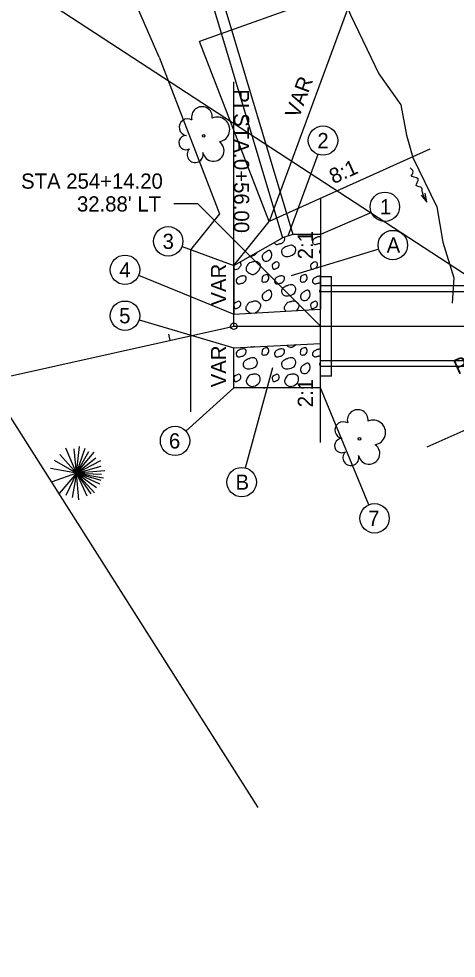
# Model space of a CAD drawing. Extents: x -1270 to 3371, y -118 to 220.
# Drawn here: x -1179.1 to -1138.8, y -9.7 to 76.8 of the extents above; entities that cross this region are included whole.
import ezdxf

# ---------------------------------------------------------------- set-up
doc = ezdxf.new("R2010")
doc.units = 0
for name, color, linetype in [('Default', 7, 'Continuous'), ('DR_P_Culvert', 7, 'Continuous'), ('GE_P_Alignment', 7, 'Continuous'), ('GE_P_Alignment_100_Bearings', 7, 'Continuous'), ('GE_P_Alignment_100_Distances', 7, 'Continuous'), ('MT_P_Edge_Line', 7, 'Continuous'), ('PF_P_Grade_Line', 7, 'Continuous'), ('PV_P_EOP', 7, 'Continuous'), ('TX_P_1', 7, 'Continuous')]:
    doc.layers.add(name, color=color, linetype=linetype)

msp = doc.modelspace()

# ---------------------------------------------------------------- linework, layer by layer
at = {"layer": 'Default'}
for p, q in [((-1166.155, 73.305), (-1175.043, 93.789)), ((-1147.999, 79.877), (-1162.424, 74.747)), ((-1147.999, 79.877), (-1156.01, 58.149)), ((-1141.191, 64.819), (-1156.01, 58.149)), ((-1151.28, 60.278), (-1151.28, 50.1)), ((-1163.28, 55.548), (-1163.28, 40.625)), ((-1159.28, 54.127), (-1159.28, 49.628)), ((-1159.28, 49.628), (-1151.28, 50.1)), ((-1213.942, 36.346), (-1159.28, 48.517)), ((-1159.28, 48.517), (-1045.28, 48.517)), ((-1157.013, 4.225), (-1184.627, 47.658)), ((-1159.28, 46.537), (-1151.28, 46.933)), ((-1151.28, 37.813), (-1151.28, 46.933)), ((-1159.28, 42.837), (-1159.28, 46.537)), ((-1131.014, 42.059), (-1141.492, 37.394)), ((-1173.764, 34.992), (-1174.76, 37.286)), ((-1173.764, 34.992), (-1173.995, 37.235)), ((-1173.764, 34.992), (-1173.485, 37.437)), ((-1173.764, 34.992), (-1172.98, 37.297)), ((-1173.764, 34.992), (-1175.312, 36.698)), ((-1173.764, 34.992), (-1172.648, 37.001)), ((-1173.764, 34.992), (-1172.157, 36.925)), ((-1173.764, 34.992), (-1171.978, 36.412)), ((-1173.764, 34.992), (-1175.809, 36.154)), ((-1173.764, 34.992), (-1171.517, 36.148)), ((-1173.764, 34.992), (-1171.491, 35.642)), ((-1173.764, 34.992), (-1176.157, 35.424)), ((-1173.764, 34.992), (-1176.011, 34.186)), ((-1173.764, 34.992), (-1175.357, 33.109)), ((-1173.764, 34.992), (-1174.747, 32.95)), ((-1173.764, 34.992), (-1174.171, 32.744)), ((-1171.152, 35.208), (-1173.764, 34.992)), ((-1173.56, 32.533), (-1173.764, 34.992)), ((-1173.764, 34.992), (-1172.808, 32.918)), ((-1173.764, 34.992), (-1172.462, 33.101)), ((-1173.764, 34.992), (-1172.11, 33.169)), ((-1173.764, 34.992), (-1171.915, 33.667)), ((-1173.764, 34.992), (-1171.667, 34.002)), ((-1173.764, 34.992), (-1171.532, 34.341)), ((-1173.764, 34.992), (-1171.291, 34.563)), ((-1173.764, 34.992), (-1171.453, 34.911))]:
    msp.add_line(p, q, dxfattribs=at)
for points in [[(-1149.472, 79.502), (-1148.517, 77.176), (-1145.899, 71.771), (-1143.882, 68.908), (-1143.359, 66.123), (-1142.764, 64.059), (-1140.563, 59.519), (-1139.997, 56.262), (-1138.983, 52.98), (-1139.134, 50.644)], [(-1159.28, 54.127), (-1156.01, 58.149), (-1162.424, 74.747)], [(-1166.155, 73.305), (-1160.577, 58.872), (-1163.28, 55.548)]]:
    msp.add_lwpolyline(points, dxfattribs=at)
for centre in [(-1162.049, 66.052), (-1147.691, 38.159)]:
    msp.add_circle(centre, 0.12, dxfattribs=at)
for centre, radius, start, end in [((-1162.209, 67.775), 0.957, 353.88223, 196.19653), ((-1163.534, 66.845), 0.776, 58.56687, 259.77452), ((-1160.789, 66.631), 1.142, 279.68449, 114.19407), ((-1163.686, 65.423), 0.658, 88.74162, 300.71103), ((-1161.159, 64.694), 0.987, 190.90911, 55.31063), ((-1162.841, 64.326), 0.735, 133.79946, 14.27816), ((-1147.852, 39.881), 0.957, 353.88223, 196.19653), ((-1146.432, 38.738), 1.142, 279.68449, 114.19407), ((-1149.176, 38.952), 0.776, 58.56687, 259.77452), ((-1149.328, 37.529), 0.658, 88.74162, 300.71103), ((-1146.802, 36.801), 0.987, 190.90911, 55.31063), ((-1148.483, 36.432), 0.735, 133.79946, 14.27816)]:
    msp.add_arc(centre, radius, start, end, dxfattribs=at)
at = {"layer": 'DR_P_Culvert'}
msp.add_line((-1159.28, 48.517), (-1159.28, 71.017), dxfattribs=at)
msp.add_circle((-1159.28, 48.517), 0.3, dxfattribs=at)
at = {"layer": 'GE_P_Alignment'}
for p, q in [((-1151.519, 64.342), (-1154.303, 56.81)), ((-1146.592, 58.982), (-1151.28, 56.954)), ((-1164.047, 55.872), (-1159.28, 54.127)), ((-1145.908, 55.601), (-1153.993, 53.152)), ((-1168.049, 53.207), (-1159.28, 49.628)), ((-1168.004, 49.106), (-1159.28, 46.537)), ((-1158.193, 35.475), (-1155.678, 44.729)), ((-1163.683, 38.87), (-1159.28, 42.837)), ((-1146.818, 32.083), (-1151.28, 42.837))]:
    msp.add_line(p, q, dxfattribs=at)
at = {"layer": 'GE_P_Alignment_100_Bearings'}
for p, q in [((-1151.28, 56.954), (-1153.824, 56.954)), ((-1151.28, 56.954), (-1151.28, 53.1)), ((-1159.28, 42.837), (-1159.28, 46.537)), ((-1151.28, 42.837), (-1151.28, 43.933)), ((-1151.28, 42.837), (-1159.28, 42.837))]:
    msp.add_line(p, q, dxfattribs=at)
msp.add_lwpolyline([(-1159.28, 49.628), (-1159.28, 54.127), (-1154.782, 56.667)], dxfattribs=at)
for points, degree in [([(-1154.643, 56.708), (-1154.641, 56.706), (-1154.639, 56.704), (-1154.637, 56.702), (-1154.576, 56.642), (-1154.585, 56.562), (-1154.603, 56.499), (-1154.632, 56.394), (-1154.671, 56.287), (-1154.773, 56.202), (-1154.873, 56.119), (-1154.979, 56.107), (-1155.087, 56.082), (-1155.199, 56.056), (-1155.328, 55.989), (-1155.438, 56.088), (-1155.493, 56.137), (-1155.515, 56.193), (-1155.522, 56.249)], 3), ([(-1151.28, 56.171), (-1151.367, 56.116), (-1151.459, 56.104), (-1151.551, 56.082), (-1151.664, 56.056), (-1151.793, 55.989), (-1151.903, 56.088), (-1151.975, 56.153), (-1151.99, 56.229), (-1151.988, 56.304), (-1151.987, 56.37), (-1151.979, 56.449), (-1151.937, 56.504), (-1151.912, 56.537), (-1151.887, 56.569), (-1151.863, 56.601)], 3), ([(-1151.863, 56.601), (-1151.779, 56.643), (-1151.696, 56.684), (-1151.613, 56.726), (-1151.521, 56.771), (-1151.412, 56.78), (-1151.312, 56.783), (-1151.301, 56.783), (-1151.291, 56.783), (-1151.28, 56.783)], 3), ([(-1151.28, 55.195), (-1151.336, 55.319), (-1151.345, 55.467), (-1151.281, 55.574), (-1151.281, 55.574), (-1151.28, 55.575), (-1151.28, 55.575)], 3), ([(-1157.15, 55.329), (-1157.169, 55.284), (-1157.195, 55.24), (-1157.231, 55.201), (-1157.364, 55.053), (-1157.512, 54.996), (-1157.677, 54.948), (-1157.745, 54.928), (-1157.818, 54.914), (-1157.89, 54.912)], 3), ([(-1158.747, 54.428), (-1158.672, 54.451), (-1158.632, 54.281), (-1158.625, 54.208), (-1158.616, 54.109), (-1158.692, 54.004), (-1158.774, 53.906), (-1158.886, 53.772), (-1159.166, 53.674), (-1159.224, 53.821), (-1159.255, 53.9), (-1159.26, 53.981), (-1159.263, 54.061), (-1159.264, 54.084), (-1159.27, 54.109), (-1159.27, 54.132)], 3), ([(-1157.827, 54.36), (-1157.708, 54.391), (-1157.59, 54.422), (-1157.471, 54.453), (-1157.298, 54.498), (-1157.123, 54.466), (-1156.95, 54.321), (-1156.816, 54.209), (-1156.807, 54.043), (-1156.843, 53.919), (-1156.888, 53.762), (-1156.986, 53.614), (-1157.138, 53.484), (-1157.328, 53.322), (-1157.592, 53.258), (-1157.787, 53.373), (-1157.944, 53.466), (-1158.111, 53.606), (-1158.141, 53.771), (-1158.16, 53.874), (-1158.106, 53.994), (-1158.046, 54.09), (-1158.003, 54.158), (-1157.964, 54.227), (-1157.908, 54.282), (-1157.881, 54.308), (-1157.854, 54.334), (-1157.827, 54.36)], 3), ([(-1151.28, 52.541), (-1151.367, 52.485), (-1151.459, 52.473), (-1151.551, 52.452), (-1151.664, 52.426), (-1151.793, 52.359), (-1151.903, 52.458), (-1151.975, 52.523), (-1151.99, 52.599), (-1151.988, 52.673), (-1151.987, 52.74), (-1151.979, 52.818), (-1151.937, 52.873), (-1151.912, 52.906), (-1151.887, 52.938), (-1151.863, 52.97)], 3), ([(-1151.863, 52.97), (-1151.779, 53.012), (-1151.696, 53.054), (-1151.613, 53.095), (-1151.521, 53.141), (-1151.412, 53.15), (-1151.312, 53.153), (-1151.301, 53.153), (-1151.291, 53.153), (-1151.28, 53.152)], 3), ([(-1151.28, 51.564), (-1151.336, 51.689), (-1151.345, 51.837), (-1151.281, 51.943), (-1151.281, 51.944), (-1151.28, 51.944), (-1151.28, 51.945)], 3), ([(-1157.739, 49.719), (-1157.755, 49.725), (-1157.771, 49.734), (-1157.787, 49.743), (-1157.944, 49.836), (-1158.111, 49.976), (-1158.141, 50.141), (-1158.16, 50.244), (-1158.106, 50.364), (-1158.046, 50.459), (-1158.003, 50.528), (-1157.964, 50.597), (-1157.908, 50.652), (-1157.881, 50.678), (-1157.854, 50.704), (-1157.827, 50.729)], 3), ([(-1157.827, 50.729), (-1157.708, 50.761), (-1157.59, 50.792), (-1157.471, 50.823), (-1157.298, 50.868), (-1157.123, 50.836), (-1156.95, 50.691), (-1156.816, 50.579), (-1156.807, 50.413), (-1156.843, 50.288), (-1156.888, 50.132), (-1156.986, 49.983), (-1157.138, 49.853), (-1157.19, 49.809), (-1157.248, 49.772), (-1157.308, 49.744)], 3), ([(-1154.472, 49.911), (-1154.539, 49.98), (-1154.59, 50.057), (-1154.605, 50.141), (-1154.624, 50.244), (-1154.571, 50.364), (-1154.51, 50.459), (-1154.467, 50.528), (-1154.429, 50.597), (-1154.372, 50.652), (-1154.345, 50.678), (-1154.318, 50.704), (-1154.291, 50.729)], 3), ([(-1154.291, 50.729), (-1154.172, 50.761), (-1154.054, 50.792), (-1153.935, 50.823), (-1153.762, 50.868), (-1153.588, 50.836), (-1153.414, 50.691), (-1153.28, 50.579), (-1153.271, 50.413), (-1153.307, 50.288), (-1153.339, 50.177), (-1153.398, 50.069), (-1153.485, 49.97)], 3), ([(-1153.539, 46.821), (-1153.559, 46.801), (-1153.58, 46.782), (-1153.603, 46.763), (-1153.793, 46.6), (-1154.057, 46.537), (-1154.251, 46.652), (-1154.311, 46.687), (-1154.372, 46.73), (-1154.427, 46.777)], 3), ([(-1157.359, 46.632), (-1157.474, 46.589), (-1157.596, 46.58), (-1157.705, 46.615)], 2), ([(-1151.28, 45.819), (-1151.367, 45.764), (-1151.459, 45.752), (-1151.551, 45.731), (-1151.664, 45.704), (-1151.793, 45.638), (-1151.903, 45.736), (-1151.975, 45.802), (-1151.99, 45.878), (-1151.988, 45.952), (-1151.987, 46.018), (-1151.979, 46.097), (-1151.937, 46.152), (-1151.912, 46.185), (-1151.887, 46.217), (-1151.863, 46.249)], 3), ([(-1151.863, 46.249), (-1151.779, 46.291), (-1151.696, 46.332), (-1151.613, 46.374), (-1151.521, 46.419), (-1151.412, 46.428), (-1151.312, 46.431), (-1151.301, 46.432), (-1151.291, 46.432), (-1151.28, 46.431)], 3), ([(-1151.28, 44.843), (-1151.336, 44.967), (-1151.345, 45.115), (-1151.281, 45.222), (-1151.281, 45.223), (-1151.28, 45.223), (-1151.28, 45.224)], 3), ([(-1156.524, 42.837), (-1156.401, 42.855), (-1156.277, 42.874), (-1156.154, 42.891), (-1156.117, 42.896), (-1156.089, 42.873), (-1156.07, 42.837)], 3), ([(-1152.988, 42.837), (-1152.865, 42.855), (-1152.742, 42.874), (-1152.618, 42.891), (-1152.581, 42.896), (-1152.554, 42.873), (-1152.534, 42.837)], 3)]:
    msp.add_open_spline(points, degree=degree, dxfattribs=at)
for points in [[(-1156.332, 55.329), (-1155.98, 55.48), (-1155.773, 55.141), (-1155.884, 54.736), (-1156.218, 54.524), (-1156.528, 54.583), (-1156.662, 54.942), (-1156.516, 55.21), (-1156.332, 55.329)], [(-1154.312, 55.911), (-1153.858, 55.987), (-1153.598, 55.607), (-1153.695, 55.201), (-1154.141, 54.948), (-1154.581, 54.951), (-1154.78, 55.129), (-1154.817, 55.574), (-1154.612, 55.787), (-1154.386, 55.896), (-1154.303, 55.913)], [(-1155.69, 54.234), (-1155.215, 54.426), (-1155.089, 54.208), (-1155.238, 53.906), (-1155.688, 53.821), (-1155.728, 54.061), (-1155.723, 54.182), (-1155.69, 54.234)], [(-1152.154, 54.234), (-1151.679, 54.426), (-1151.553, 54.208), (-1151.703, 53.906), (-1152.153, 53.821), (-1152.192, 54.061), (-1152.188, 54.182), (-1152.154, 54.234)], [(-1158.934, 52.97), (-1158.684, 53.095), (-1158.383, 53.153), (-1158.173, 53.072), (-1158.138, 52.868), (-1158.309, 52.572), (-1158.623, 52.452), (-1158.974, 52.458), (-1159.06, 52.673), (-1159.008, 52.873), (-1158.934, 52.97)], [(-1156.536, 53.187), (-1156.154, 53.243), (-1156.05, 52.914), (-1156.29, 52.62), (-1156.677, 52.677), (-1156.674, 52.923), (-1156.616, 53.086), (-1156.536, 53.187)], [(-1155.398, 52.97), (-1155.148, 53.095), (-1154.848, 53.153), (-1154.637, 53.072), (-1154.603, 52.868), (-1154.773, 52.572), (-1155.087, 52.452), (-1155.438, 52.458), (-1155.524, 52.673), (-1155.473, 52.873), (-1155.398, 52.97)], [(-1153, 53.187), (-1152.618, 53.243), (-1152.514, 52.914), (-1152.754, 52.62), (-1153.141, 52.677), (-1153.138, 52.923), (-1153.08, 53.086), (-1153, 53.187)], [(-1154.312, 52.281), (-1153.858, 52.357), (-1153.598, 51.977), (-1153.695, 51.57), (-1154.141, 51.318), (-1154.581, 51.32), (-1154.78, 51.498), (-1154.817, 51.943), (-1154.612, 52.157), (-1154.386, 52.265), (-1154.303, 52.283)], [(-1156.332, 51.698), (-1155.98, 51.849), (-1155.773, 51.511), (-1155.884, 51.106), (-1156.218, 50.893), (-1156.528, 50.953), (-1156.662, 51.312), (-1156.516, 51.579), (-1156.332, 51.698)], [(-1152.796, 51.698), (-1152.444, 51.849), (-1152.237, 51.511), (-1152.348, 51.106), (-1152.682, 50.893), (-1152.993, 50.953), (-1153.126, 51.312), (-1152.98, 51.579), (-1152.796, 51.698)], [(-1159.226, 50.603), (-1158.751, 50.796), (-1158.625, 50.578), (-1158.774, 50.275), (-1159.224, 50.191), (-1159.263, 50.431), (-1159.259, 50.552), (-1159.226, 50.603)], [(-1152.154, 50.603), (-1151.679, 50.796), (-1151.553, 50.578), (-1151.703, 50.275), (-1152.153, 50.191), (-1152.192, 50.431), (-1152.188, 50.552), (-1152.154, 50.603)], [(-1158.934, 46.249), (-1158.684, 46.374), (-1158.383, 46.431), (-1158.173, 46.351), (-1158.138, 46.147), (-1158.309, 45.851), (-1158.623, 45.731), (-1158.974, 45.736), (-1159.06, 45.952), (-1159.008, 46.152), (-1158.934, 46.249)], [(-1156.536, 46.466), (-1156.154, 46.521), (-1156.05, 46.193), (-1156.29, 45.899), (-1156.677, 45.956), (-1156.674, 46.201), (-1156.616, 46.365), (-1156.536, 46.466)], [(-1155.398, 46.249), (-1155.148, 46.374), (-1154.848, 46.431), (-1154.637, 46.351), (-1154.603, 46.147), (-1154.773, 45.851), (-1155.087, 45.731), (-1155.438, 45.736), (-1155.524, 45.952), (-1155.473, 46.152), (-1155.398, 46.249)], [(-1153, 46.466), (-1152.618, 46.521), (-1152.514, 46.193), (-1152.754, 45.899), (-1153.141, 45.956), (-1153.138, 46.201), (-1153.08, 46.365), (-1153, 46.466)], [(-1157.848, 45.56), (-1157.393, 45.636), (-1157.134, 45.256), (-1157.231, 44.849), (-1157.677, 44.596), (-1158.117, 44.599), (-1158.316, 44.777), (-1158.353, 45.222), (-1158.148, 45.436), (-1157.922, 45.544), (-1157.839, 45.561)], [(-1154.312, 45.56), (-1153.858, 45.636), (-1153.598, 45.256), (-1153.695, 44.849), (-1154.141, 44.596), (-1154.581, 44.599), (-1154.78, 44.777), (-1154.817, 45.222), (-1154.612, 45.436), (-1154.386, 45.544), (-1154.303, 45.561)], [(-1152.796, 44.977), (-1152.444, 45.128), (-1152.237, 44.79), (-1152.348, 44.385), (-1152.682, 44.172), (-1152.993, 44.231), (-1153.126, 44.591), (-1152.98, 44.858), (-1152.796, 44.977)], [(-1159.226, 43.882), (-1158.751, 44.075), (-1158.625, 43.856), (-1158.774, 43.554), (-1159.224, 43.47), (-1159.263, 43.71), (-1159.259, 43.831), (-1159.226, 43.882)], [(-1157.827, 44.008), (-1157.471, 44.101), (-1156.95, 43.97), (-1156.843, 43.567), (-1157.138, 43.132), (-1157.787, 43.021), (-1158.141, 43.42), (-1158.046, 43.738), (-1157.908, 43.931), (-1157.827, 44.008)], [(-1155.69, 43.882), (-1155.215, 44.075), (-1155.089, 43.856), (-1155.238, 43.554), (-1155.688, 43.47), (-1155.728, 43.71), (-1155.723, 43.831), (-1155.69, 43.882)], [(-1154.291, 44.008), (-1153.935, 44.101), (-1153.414, 43.97), (-1153.307, 43.567), (-1153.603, 43.132), (-1154.251, 43.021), (-1154.605, 43.42), (-1154.51, 43.738), (-1154.372, 43.931), (-1154.291, 44.008)]]:
    msp.add_spline(points, degree=3, dxfattribs=at)
at = {"layer": 'GE_P_Alignment_100_Distances'}
for p, q in [((-1142.016, 60.575), (-1141.474, 59.949)), ((-1141.474, 59.949), (-1141.63, 60.763))]:
    msp.add_line(p, q, dxfattribs=at)
msp.add_spline([(-1141.474, 59.949), (-1141.835, 60.698), (-1141.911, 61.027), (-1141.937, 61.246), (-1142.453, 61.467), (-1142.294, 62.083), (-1142.909, 62.407), (-1142.758, 62.606), (-1143.003, 63.098)], degree=3, dxfattribs=at)
at = {"layer": 'PF_P_Grade_Line'}
for p, q in [((-1167.971, 100.736), (-1154.782, 56.667)), ((-1167.013, 101.022), (-1153.824, 56.954)), ((-1153.824, 56.954), (-1154.782, 56.667)), ((-1151.28, 43.933), (-1151.28, 53.1)), ((-1151.28, 53.1), (-1150.28, 53.1)), ((-1150.28, 43.933), (-1150.28, 53.1)), ((-1077.28, 52.225), (-1151.28, 52.225)), ((-1077.28, 51.683), (-1151.28, 51.683)), ((-1077.28, 45.35), (-1151.28, 45.35)), ((-1077.321, 44.808), (-1151.28, 44.808)), ((-1150.28, 43.933), (-1151.28, 43.933))]:
    msp.add_line(p, q, dxfattribs=at)
at = {"layer": 'PV_P_EOP'}
msp.add_line((-1165.137, 47.213), (-1165.267, 47.798), dxfattribs=at)
at = {"layer": 'TX_P_1'}
for p, q in [((-1261.123, 133.662), (-876.009, -117.627)), ((-1162.589, 59.782), (-1164.806, 59.782)), ((-1151.28, 48.517), (-1162.589, 59.782))]:
    msp.add_line(p, q, dxfattribs=at)
for centre in [(-1151.049, 65.613), (-1145.349, 59.52), (-1165.319, 56.338), (-1144.612, 55.994), (-1169.303, 53.718), (-1169.303, 49.488), (-1164.689, 37.963), (-1158.548, 34.168), (-1146.299, 30.832)]:
    msp.add_circle(centre, 1.355, dxfattribs=at)

# ---------------------------------------------------------------- texts
at = {"layer": 'DR_P_Culvert'}
for s, p in [('PI', (-1159.259, 70.346)), (' STA. ', (-1159.259, 68.651)), ('0+56.00', (-1159.259, 63.925))]:
    msp.add_text(s, height=1.4, rotation=270, dxfattribs=at).set_placement(p)
at = {"layer": 'MT_P_Edge_Line'}
msp.add_text('PC', height=1.4, rotation=24, dxfattribs=at).set_placement((-1138.627, 44.044))
at = {"layer": 'TX_P_1'}
for s, rotation, p in [('VAR', 69.76121, (-1153.28, 67.577)), ('8:1', 24.23101, (-1150.084, 61.584)), ('2:1', 90, (-1151.98, 54.681)), ('VAR', 90, (-1159.98, 50.421)), ('VAR', 90, (-1159.98, 42.898)), ('2:1', 90, (-1151.98, 41.061))]:
    msp.add_text(s, height=1.4, rotation=rotation, dxfattribs=at).set_placement(p)
for s, p in [('2', (-1151.571, 64.913)), ('STA 254+14.20', (-1178.879, 61.182)), ("32.88' LT", (-1173.731, 59.082)), ('1', (-1145.807, 58.82)), ('3', (-1165.838, 55.638)), ('A', (-1145.184, 55.294)), ('4', (-1169.822, 53.018)), ('5', (-1169.839, 48.788)), ('6', (-1165.251, 37.263)), ('B', (-1159.114, 33.468)), ('7', (-1146.89, 30.132))]:
    msp.add_text(s, height=1.4, dxfattribs=at).set_placement(p)

doc.saveas('drawing.dxf')
